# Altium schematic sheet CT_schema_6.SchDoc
size 364 x 333 mm
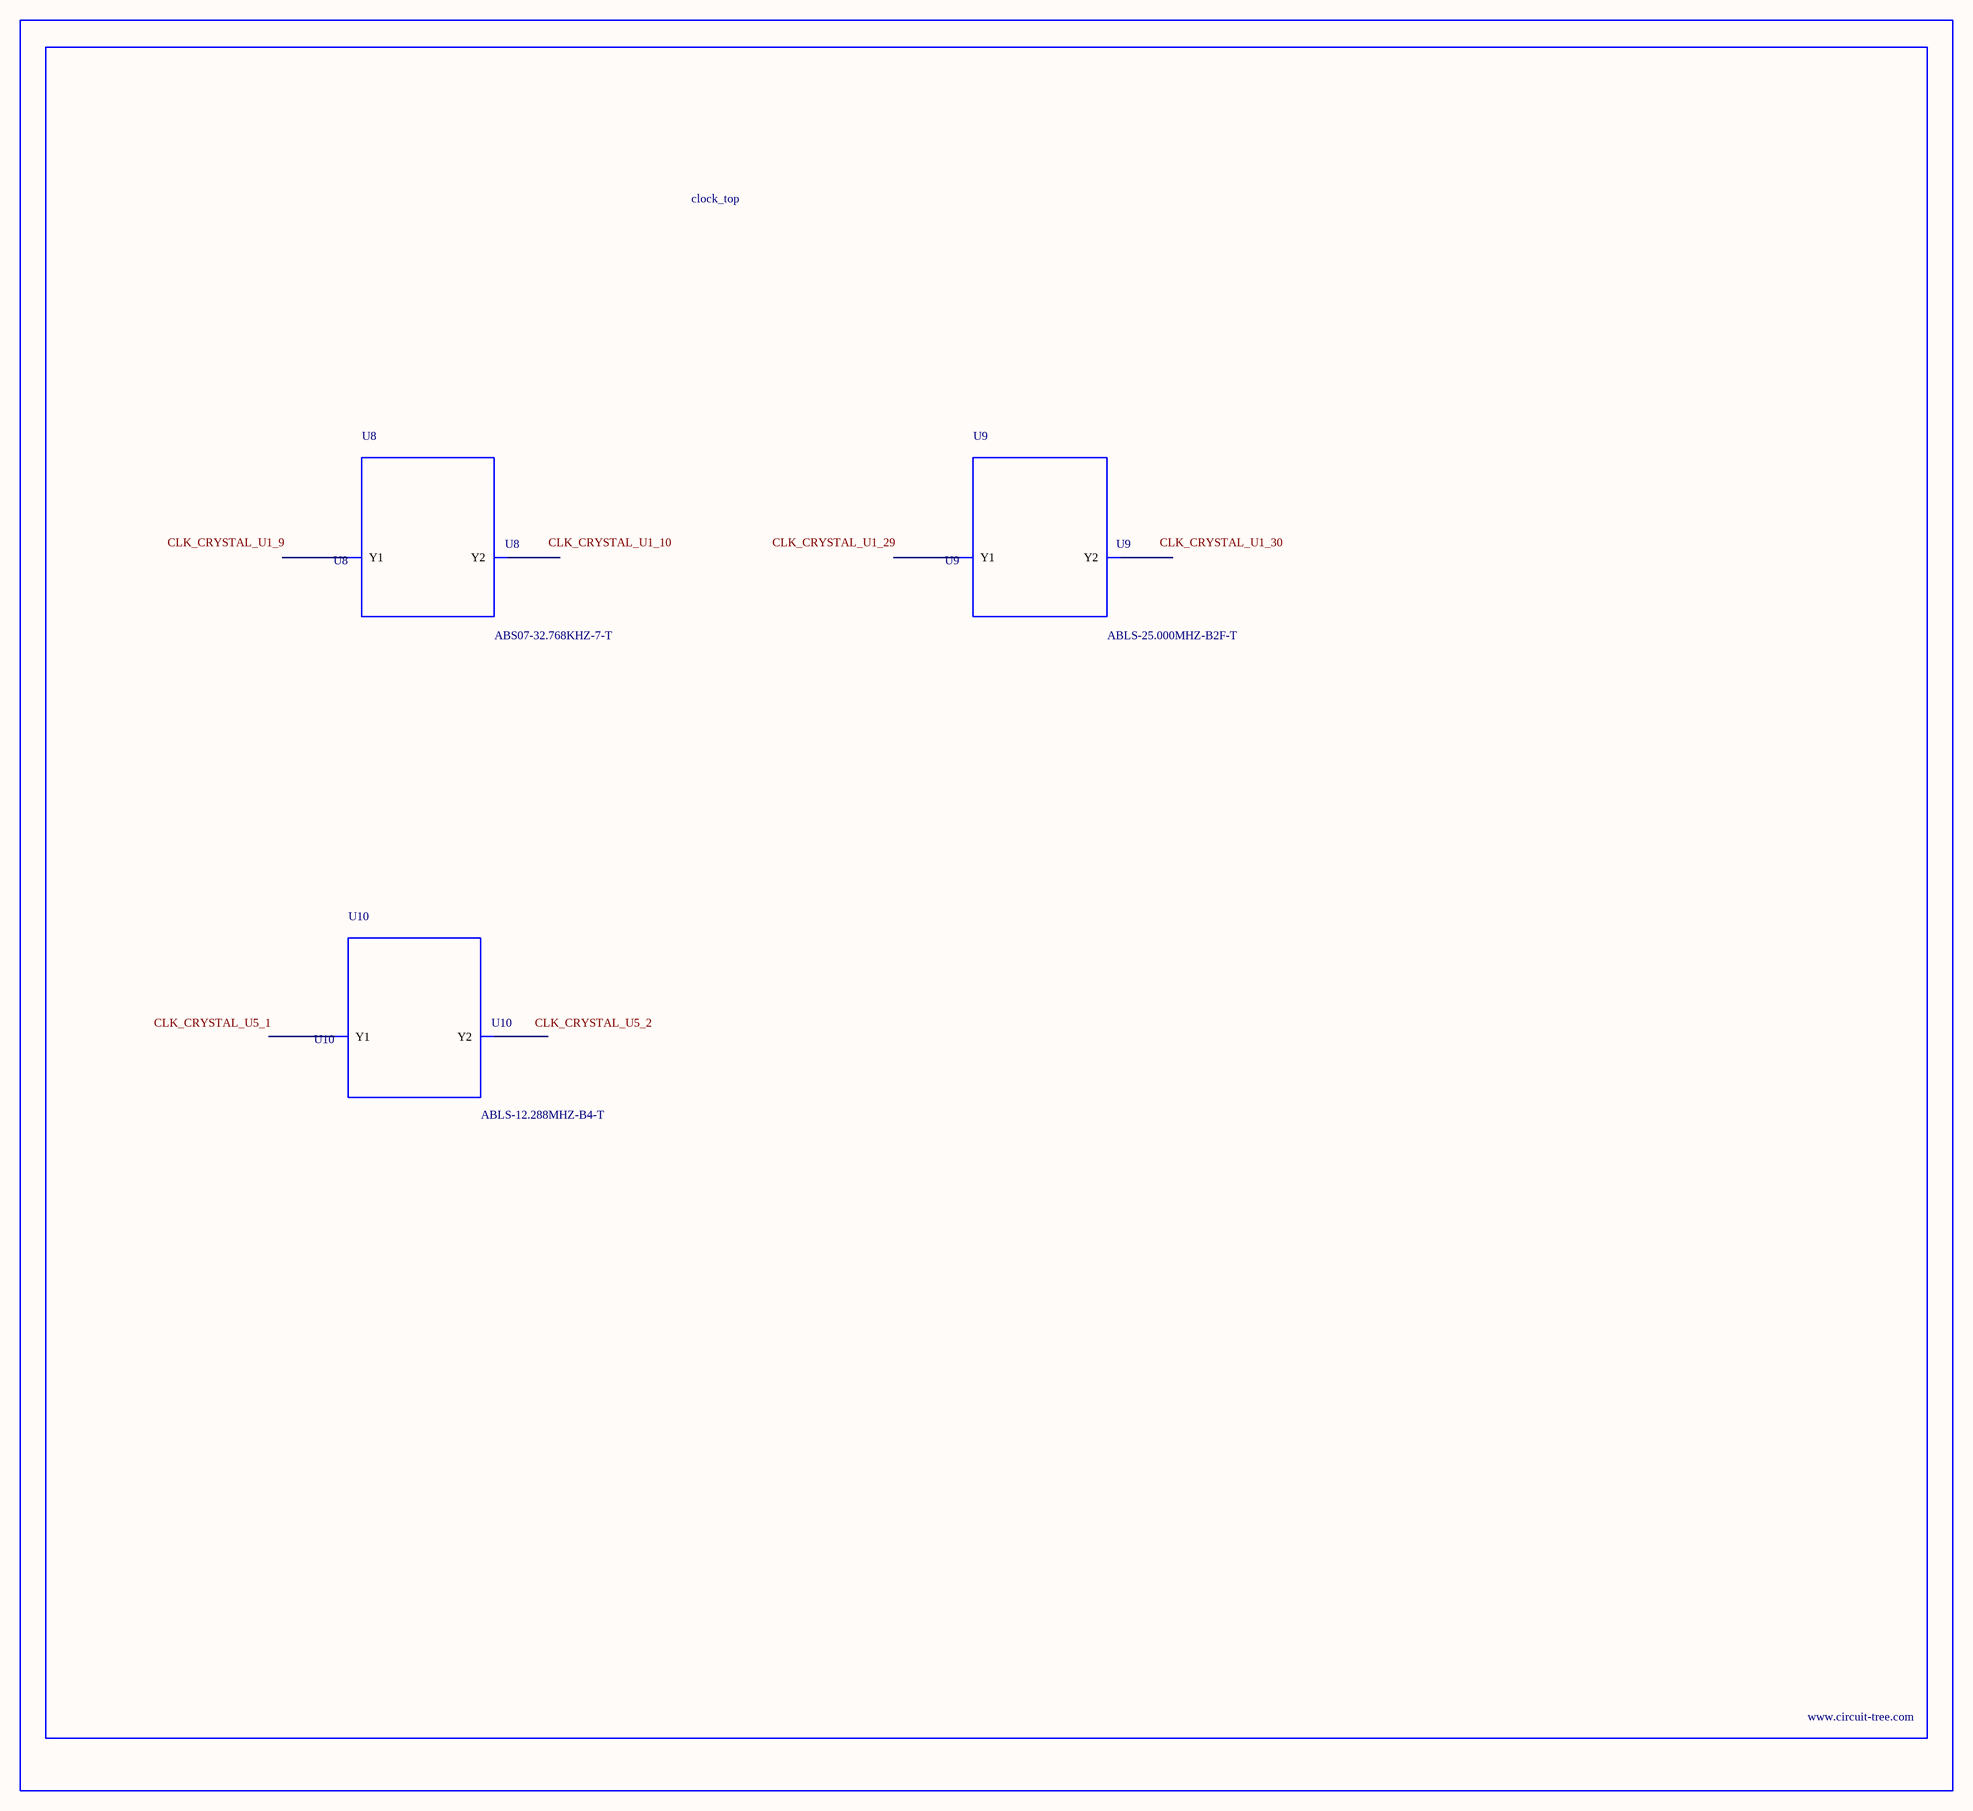
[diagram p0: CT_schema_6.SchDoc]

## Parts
BORDER5  (no value)
U8  ABS07-32.768KHZ-7-T  [ABS07-32.768KHZ-7-T]
U9  ABLS-25.000MHZ-B2F-T  [ABLS-25.000MHZ-B2F-T]
U10  ABLS-12.288MHZ-B4-T  [ABLS-12.288MHZ-B4-T]

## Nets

Not connected (* = marked no-connect by the designer): U8 1(Y1) 2(Y2); U9 1(Y1) 2(Y2); U10 1(Y1) 2(Y2)

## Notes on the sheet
- Labels drawn without touching a wire or pin: CLK_CRYSTAL_U1_9, CLK_CRYSTAL_U1_10, CLK_CRYSTAL_U1_29, CLK_CRYSTAL_U1_30, CLK_CRYSTAL_U5_1, CLK_CRYSTAL_U5_2

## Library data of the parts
BORDER5 = BORDER_PAGE5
